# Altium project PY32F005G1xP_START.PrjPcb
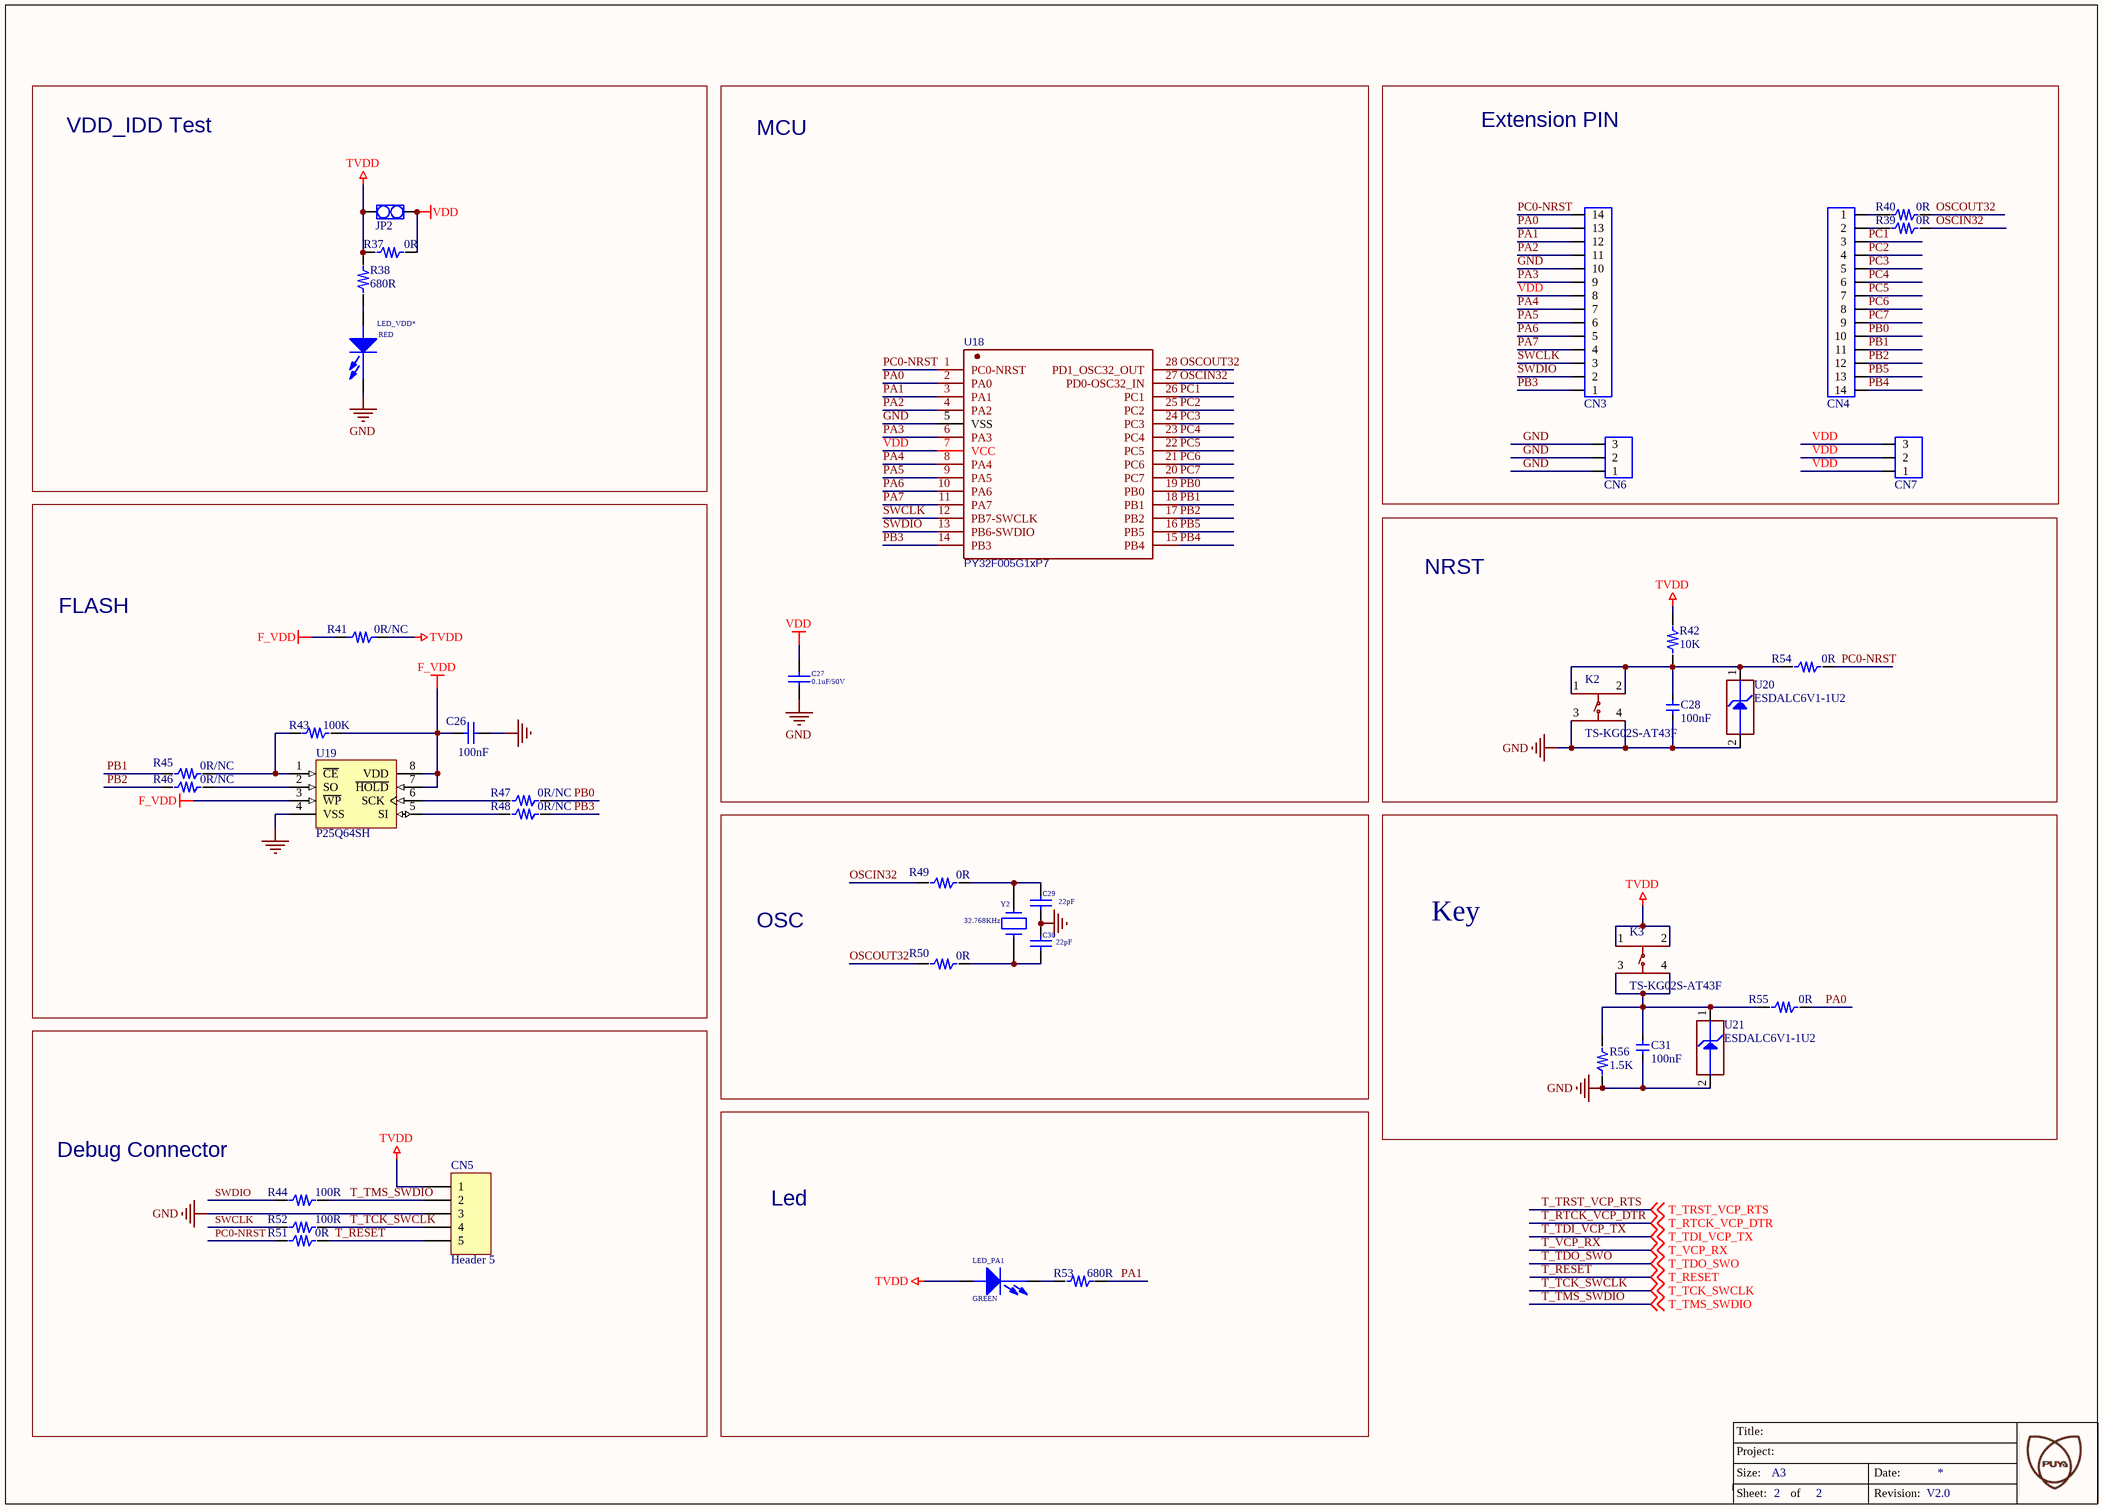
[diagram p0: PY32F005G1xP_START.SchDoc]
2 sheets, 129 parts. Net scope: global (net labels, ports and power ports of the same name join across sheets).
Board file: PY32F005G1xP_START.PcbDoc
Sheets:
  PY32F005G1xP_START.SchDoc
  PY32F403C1xT_LINK.SchDoc

## Sheet PY32F005G1xP_START.SchDoc: =DocumentName
size A3; Revision: V2.0; SheetNumber: 2; SheetTotal: 2; Project: PY32F005G1xP_START.PrjPcb

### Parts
C26  100nF  [C0603]
C27  0.1uF/50V  [0603C]
C28  100nF  [C0603]
C29  22pF  [0603C]
C30  22pF  [0603C]
C31  100nF  [C0603]
CN3  CON14  [CON14]  (value not drawn)
CN4  CON14  [CON14]  (value not drawn)
CN5  Header 5  [HDR1X5]
CN6  CON3  [CON3]  (value not drawn)
CN7  CON3  [CON3]  (value not drawn)
JP2  CON2  [CON2]  (value not drawn)
K2  TS-KG02S-AT43F  [SW-SMD_4P-L6.0-W6.0-P4.50-LS8.5]
K3  TS-KG02S-AT43F  [SW-SMD_4P-L6.0-W6.0-P4.50-LS8.5]
LED_PA1  GREEN  [0603_LED]
LED_VDD*  RED  [0603_LED]
R37  0R  [JP2_SMD]
R38  680R  [R0603]
R39  0R  [JP2_SMD]
R40  0R  [JP2_SMD]
R41  0R/NC  [JP2_SMD]
R42  10K  [R0603]
R43  100K  [R0603]
R44  100R  [JP2_SMD]
R45  0R/NC  [JP2_SMD]
R46  0R/NC  [JP2_SMD]
R47  0R/NC  [JP2_SMD]
R48  0R/NC  [JP2_SMD]
R49  0R  [JP2_SMD]
R50  0R  [JP2_SMD]
R51  0R  [JP2_SMD]
R52  100R  [JP2_SMD]
R53  680R  [R0603]
R54  0R  [JP2_SMD]
R55  0R  [JP2_SMD]
R56  1.5K  [R0603]
U18  PY32F005G1xP7  [TSSOP-28_L9.7-W4.4-P0.65-LS6.4-BL]
U19  P25Q64SH  [SOP-8P]
U20  ESDALC6V1-1U2  [ESD_ST0201]
U21  ESDALC6V1-1U2  [ESD_ST0201]
Y2  32.768KHz  [CRYSTAL-SMD_L3.2-W1.5-1]

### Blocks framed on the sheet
VDD_IDD Test: JP2 LED_VDD* R37 R38
MCU: C27 U18
Extension PIN: CN3 CN4 CN6 CN7 R39 R40
FLASH: C26 R41 R43 R45-R48 U19
NRST: C28 K2 R42 R54 U20
OSC: C29 C30 R49 R50 Y2
Key: C31 K3 R55 R56 U21
Debug Connector: CN5 R44 R51 R52
Led: LED_PA1 R53

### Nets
F_VDD: C26.2 R41.2 R43.2 U19.3(~{WP}) U19.7(~{HOLD}) U19.8(VDD)
GND: C26.1 C27.1 C28.1 C29.1 C30.2 C31.1 CN3.10 CN5.3 CN6.1 CN6.2 CN6.3 K2.3 K2.4 LED_VDD*.2(CATHODE) R56.1 U18.5(VSS) U19.4(VSS) U20.2(GND) U21.2(GND)
TVDD: CN5.1 JP2.1 K3.1 K3.2 LED_PA1.1(ANODE) R37.1 R38.2 R41.1 R42.1
VDD: C27.2 CN3.8 CN7.1 CN7.2 CN7.3 JP2.2 R37.2 U18.7(VCC)
OSCIN32: R39.1 R49.2 U18.27(PD0-OSC32_IN)
OSCOUT32: R40.1 R50.2 U18.28(PD1_OSC32_OUT)
PA0: CN3.13 R55.2 U18.2(PA0)
PA1: CN3.12 R53.2 U18.3(PA1)
PA2: CN3.11 U18.4(PA2)
PA3: CN3.9 U18.6(PA3)
PA4: CN3.7 U18.8(PA4)
PA5: CN3.6 U18.9(PA5)
PA6: CN3.5 U18.10(PA6)
PA7: CN3.4 U18.11(PA7)
PB0: CN4.10 R47.1 U18.19(PB0)
PB1: CN4.11 R45.2 U18.18(PB1)
PB2: CN4.12 R46.2 U18.17(PB2)
PB3: CN3.1 R48.1 U18.14(PB3)
PB4: CN4.14 U18.15(PB4)
PB5: CN4.13 U18.16(PB5)
PC0-NRST: CN3.14 R51.2 R54.2 U18.1(PC0-NRST)
PC1: CN4.3 U18.26(PC1)
PC2: CN4.4 U18.25(PC2)
PC3: CN4.5 U18.24(PC3)
PC4: CN4.6 U18.23(PC4)
PC5: CN4.7 U18.22(PC5)
PC6: CN4.8 U18.21(PC6)
PC7: CN4.9 U18.20(PC7)
SWCLK: CN3.3 R52.2 U18.12(PB7-SWCLK)
SWDIO: CN3.2 R44.2 U18.13(PB6-SWDIO)
T_RESET: CN5.5 R51.1 ; off-sheet T_RESET
T_TCK_SWCLK: CN5.4 R52.1 ; off-sheet T_TCK_SWCLK
T_TMS_SWDIO: CN5.2 R44.1 ; off-sheet T_TMS_SWDIO
NetC28_2: C28.2 K2.1 K2.2 R42.2 R54.1 U20.1(IO1)
NetC29_2: C29.2 R49.1 Y2.1
NetC30_1: C30.1 R50.1 Y2.2
NetC31_2: C31.2 K3.3 K3.4 R55.1 R56.2 U21.1(IO1)
NetCN4_1: CN4.1 R40.2
NetCN4_2: CN4.2 R39.2
NetLED_PA1_2: LED_PA1.2(CATHODE) R53.1
NetLED_VDD*_1: LED_VDD*.1(ANODE) R38.1
NetR43_1: R43.1 R45.1 U19.1(~{CE})
NetR46_1: R46.1 U19.2(SO)
NetR47_2: R47.2 U19.6(SCK)
NetR48_2: R48.2 U19.5(SI)

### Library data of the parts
C26 = 贴片高压陶瓷电容: Capacitor (Semiconductor SIM Model); 器件封装(外观): 0603; Value: 104
C27 = CAP: Capacitor; Value: 2.2uF
C28 C31 = C0603: PCB DECAL: 0603
C29 C30 = Cap: Capacitor
CN5 = Header 5: Header, 5-Pin
JP2 = CON2_DIP
K2 K3 = TS-KG02S-AT43F: Manufacturer: HANBO(汉博); Add into BOM: yes; Circuit: 单刀单掷; Actuator Style: 圆形按钮; Operating Force: 250gf; Switch Length: 6mm; Switch Height: 4.3mm; Strike Gundam: 不带; Contact Current: 50mA; Voltage Rating (DC): 12V; Insulation Resistance: 100MΩ; Actuator/Cap Color: 黑色; Pin Style: 鸥翼型
LED_PA1 LED_VDD* = PDI-E803_Dup1
R37-R56 = R0603: PCB DECAL: 0603
U18 = PY32F005G1xP7: TSSOP28(9.7*4.4); BOM_Manufacturer: PUYA(普冉)
U19 = SST25VF010: Value: SST25VF020B; 器件封装(外观): SOP8
U20 U21 = ESDALC6V1-1U2: ESD protection 6V1; Internal_Part_Number: MCD-00170; Part_Type: Diode; Manufacturer: STMICROELECTRONICS; ECCN_US: EAR99; ECCN_EU: NEC; Provided_By: Subcon; Initial_Board_Reference: MB1274
Y2 = CRYSTAL_1: Crystal; Value: X503225MSB2GI

## Sheet PY32F403C1xT_LINK.SchDoc: =DocumentName
size A3; Revision: V2.0; SheetNumber: 1; SheetTotal: 2; Project: PY32F005G1xP_START.PrjPcb
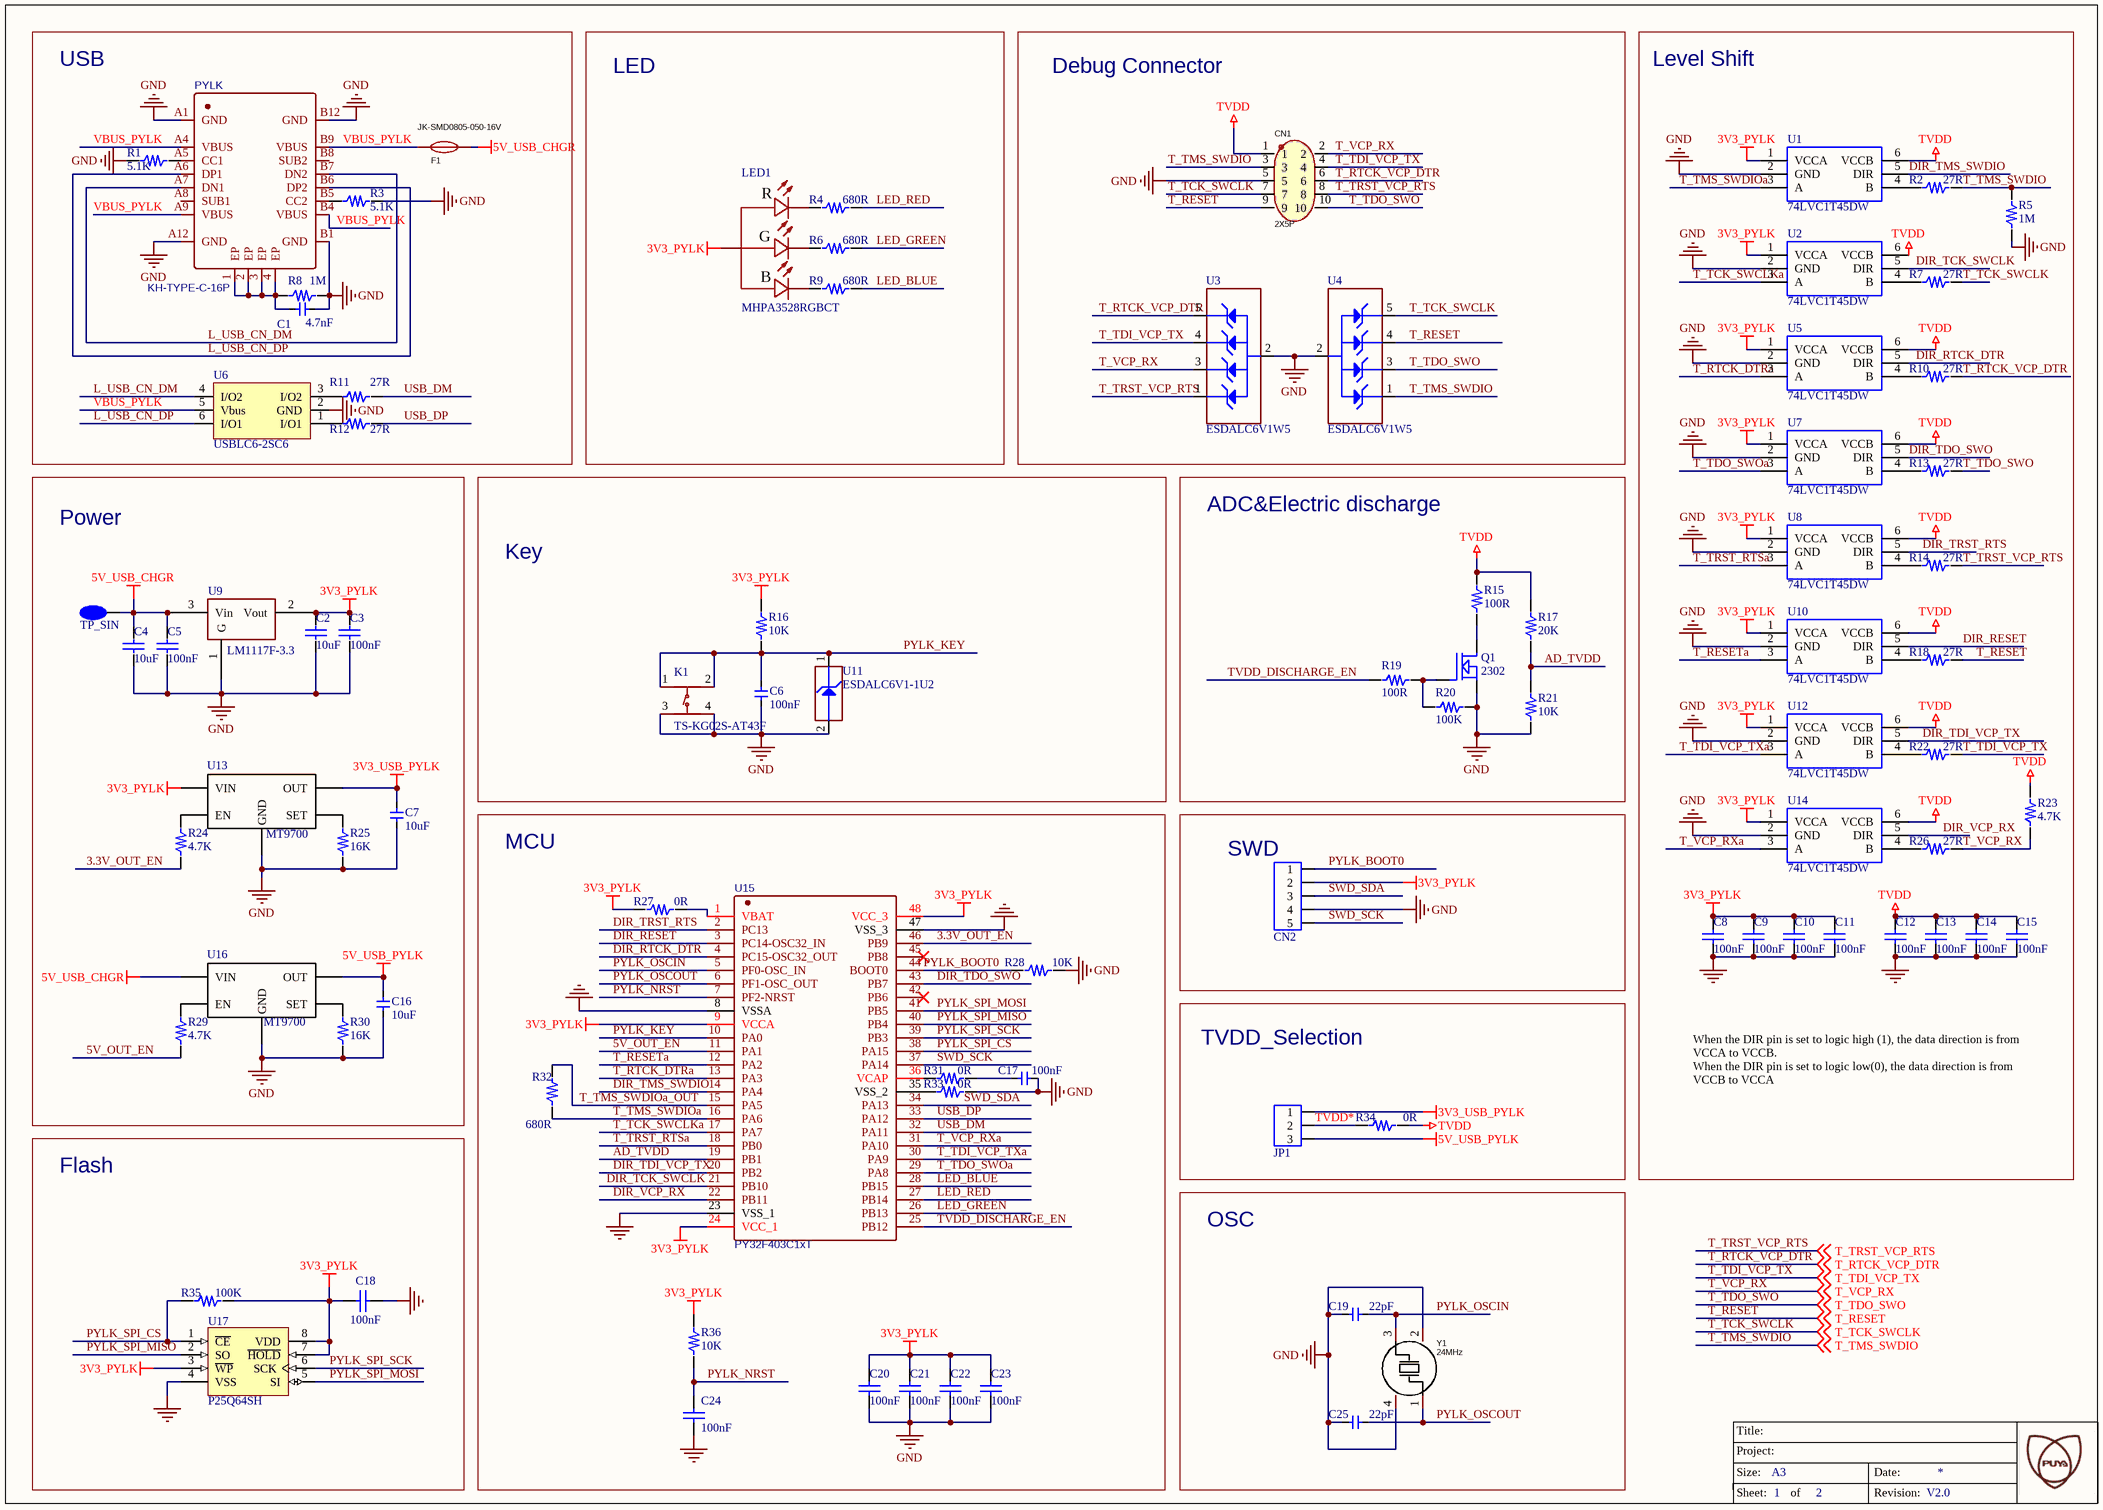
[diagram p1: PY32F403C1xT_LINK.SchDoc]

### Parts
1  TP_SIN  [TP_SIN]
C1  4.7nF  [C0603]
C2  10uF  [C0805]
C3  100nF  [C0603]
C4  10uF  [C0805]
C5  100nF  [C0603]
C6  100nF  [C0603]
C7  10uF  [C0805]
C8  100nF  [C0603]
C9  100nF  [C0603]
C10  100nF  [C0603]
C11  100nF  [C0603]
C12  100nF  [C0603]
C13  100nF  [C0603]
C14  100nF  [C0603]
C15  100nF  [C0603]
C16  10uF  [C0805]
C17  100nF  [C0603]
C18  100nF  [C0603]
C19  22pF  [C0603]
C20  100nF  [C0603]
C21  100nF  [C0603]
C22  100nF  [C0603]
C23  100nF  [C0603]
C24  100nF  [C0603]
C25  22pF  [C0603]
CN1  2X5P  [HDR2X5]
CN2  CON5  [CON5]  (value not drawn)
F1  JK-SMD0805-050-16V  [F0805]
JP1  CON3  [CON3]  (value not drawn)
K1  TS-KG02S-AT43F  [SW-SMD_4P-L6.0-W6.0-P4.50-LS8.5]
LED1  MHPA3528RGBCT  [LED-ARRAY-SMD_4P-L3.5-W2.8-TL]
PYLK  KH-TYPE-C-16P  [USB-C-SMD_KH-TYPE-C-16P]
Q1  2302  [SOT23]
R1  5.1K  [R0603]
R2  27R  [R0603]
R3  5.1K  [R0603]
R4  680R  [R0603]
R5  1M  [R0603]
R6  680R  [R0603]
R7  27R  [R0603]
R8  1M  [R0603]
R9  680R  [R0603]
R10  27R  [R0603]
R11  27R  [R0603]
R12  27R  [R0603]
R13  27R  [R0603]
R14  27R  [R0603]
R15  100R  [R0805]
R16  10K  [R0603]
R17  20K  [R0603]
R18  27R  [R0603]
R19  100R  [R0603]
R20  100K  [R0603]
R21  10K  [R0603]
R22  27R  [R0603]
R23  4.7K  [R0603]
R24  4.7K  [R0603]
R25  16K  [R0603]
R26  27R  [R0603]
R27  0R  [JP2_SMD]
R28  10K  [R0603]
R29  4.7K  [R0603]
R30  16K  [R0603]
R31  0R  [JP2_SMD]
R32  680R  [R0603]
R33  0R  [JP2_SMD]
R34  0R  [JP2_SMD]
R35  100K  [R0603]
R36  10K  [R0603]
U1  74LVC1T45DW  [SOT363]
U2  74LVC1T45DW  [SOT363]
U3  value ESDALC6V1W5  [ESD_SOT323-5L]  (hidden comment: ESD_6V1)
U4  value ESDALC6V1W5  [ESD_SOT323-5L]  (hidden comment: ESD_6V1)
U5  74LVC1T45DW  [SOT363]
U6  USBLC6-2SC6  [SOT23-6]
U7  74LVC1T45DW  [SOT363]
U8  74LVC1T45DW  [SOT363]
U9  LM1117F-3.3  [SOT-89-3_L4.5-W2.5-P1.50-LS4.2-BR]
U10  74LVC1T45DW  [SOT363]
U11  ESDALC6V1-1U2  [ESD_ST0201]
U12  74LVC1T45DW  [SOT363]
U13  MT9700  [SOT23-5]
U14  74LVC1T45DW  [SOT363]
U15  PY32F403C1xT  [LQFP-48_L7.0-W7.0-P0.50-LS9.0-BL]
U16  MT9700  [SOT23-5]
U17  P25Q64SH  [SOP-8P]
Y1  24MHz  [CRYSTAL-SMD_4P-L3.2-W2.5-BL]

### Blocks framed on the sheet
USB: C1 F1 PYLK R1 R3 R8 R11 R12 U6
LED: LED1 R4 R6 R9
Debug Connector: CN1 U3 U4
Level Shift: C8-C15 R2 R5 R7 R10 R13 R14 R18 R22 R23 R26 U1 U2 U5 U7 U8 U10 U12 U14
Power: 1 C2-C5 C7 C16 R24 R25 R29 R30 U9 U13 U16
Key: C6 K1 R16 U11
ADC&Electric discharge: Q1 R15 R17 R19-R21
MCU: C17 C20-C24 R27 R28 R31-R33 R36 U15
SWD: CN2
TVDD_Selection: JP1 R34
Flash: C18 R35 U17
OSC: C19 C25 Y1

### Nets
3V3_PYLK: C2.2 C3.2 C8.2 C9.2 C10.2 C11.2 C18.2 C20.2 C21.2 C22.2 C23.2 CN2.2 LED1.1(-) R16.2 R27.1 R35.2 R36.2 U1.1(VCCA) U2.1(VCCA) U5.1(VCCA) U7.1(VCCA) U8.1(VCCA) U9.2(Vout) U10.1(VCCA) U12.1(VCCA) U13.5(VIN) U14.1(VCCA) U15.9(VCCA) U15.24(VCC_1) U15.48(VCC_3) U17.3(~{WP}) U17.7(~{HOLD}) U17.8(VDD)
3V3_USB_PYLK: C7.2 JP1.1 U13.1(OUT)
5V_USB_CHGR: 1.1(TP_SIN) C4.2 C5.2 F1.2 U9.3(Vin) U16.5(VIN)
5V_USB_PYLK: C16.2 JP1.3 U16.1(OUT)
GND: C1.1 C2.1 C3.1 C4.1 C5.1 C6.1 C7.1 C8.1 C9.1 C10.1 C11.1 C12.1 C13.1 C14.1 C15.1 C16.1 C17.1 C18.1 C19.1 C20.1 C21.1 C22.1 C23.1 C24.1 C25.1 CN1.5 CN2.4 K1.3 K1.4 PYLK.A1(GND) PYLK.A12(GND) PYLK.B1(GND) PYLK.B12(GND) Q1.2(S) R1.1 R3.2 R5.1 R8.2 R20.1 R21.1 R25.1 R28.2 R30.1 R33.2 U1.2(GND) U2.2(GND) U3.2(GND) U4.2(GND) U5.2(GND) U6.2(GND) U7.2(GND) U8.2(GND) U9.1(G) U10.2(GND) U11.2(GND) U12.2(GND) U13.2(GND) U14.2(GND) U15.8(VSSA) U15.23(VSS_1) U15.47(VSS_3) U16.2(GND) U17.4(VSS) Y1.2(GND) Y1.4(GND)
TVDD: C12.2 C13.2 C14.2 C15.2 CN1.1 R15.2 R17.2 R23.2 R34.2 U1.6(VCCB) U2.6(VCCB) U5.6(VCCB) U7.6(VCCB) U8.6(VCCB) U10.6(VCCB) U12.6(VCCB) U14.6(VCCB)
3.3V_OUT_EN: R24.1 U15.46(PB9)
5V_OUT_EN: R29.1 U15.11(PA1)
AD_TVDD: R17.1 R21.2 U15.19(PB1)
DIR_RESET: U10.5(DIR) U15.3(PC14-OSC32_IN)
DIR_RTCK_DTR: U5.5(DIR) U15.4(PC15-OSC32_OUT)
DIR_TCK_SWCLK: U2.5(DIR) U15.21(PB10)
DIR_TDI_VCP_TX: U12.5(DIR) U15.20(PB2)
DIR_TDO_SWO: U7.5(DIR) U15.43(PB7)
DIR_TMS_SWDIO: U1.5(DIR) U15.14(PA4)
DIR_TRST_RTS: U8.5(DIR) U15.2(PC13)
DIR_VCP_RX: U14.5(DIR) U15.22(PB11)
L_USB_CN_DM: PYLK.A7(DN1) PYLK.B7(DN2) U6.4(I/O2)
L_USB_CN_DP: PYLK.A6(DP1) PYLK.B6(DP2) U6.6(I/O1)
LED_BLUE: R9.2 U15.28(PB15)
LED_GREEN: R6.2 U15.26(PB13)
LED_RED: R4.2 U15.27(PB14)
PYLK_BOOT0: CN2.1 R28.1 U15.44(BOOT0)
PYLK_KEY: C6.2 K1.1 K1.2 R16.1 U11.1(IO1) U15.10(PA0)
PYLK_NRST: C24.2 R36.1 U15.7(PF2-NRST)
PYLK_OSCIN: C19.2 U15.5(PF0-OSC_IN) Y1.3(OSC2)
PYLK_OSCOUT: C25.2 U15.6(PF1-OSC_OUT) Y1.1(OSC1)
PYLK_SPI_CS: R35.1 U15.38(PA15) U17.1(~{CE})
PYLK_SPI_MISO: U15.40(PB4) U17.2(SO)
PYLK_SPI_MOSI: U15.41(PB5) U17.5(SI)
PYLK_SPI_SCK: U15.39(PB3) U17.6(SCK)
SWD_SCK: CN2.5 U15.37(PA14)
SWD_SDA: CN2.3 U15.34(PA13)
T_RESET: CN1.9 R18.2 U4.4(IO3) ; off-sheet T_RESET
T_RESETa: U10.3(A) U15.12(PA2)
T_RTCK_DTRa: U5.3(A) U15.13(PA3)
T_RTCK_VCP_DTR: CN1.6 R10.2 U3.5(IO4) ; off-sheet T_RTCK_VCP_DTR
T_TCK_SWCLK: CN1.7 R7.2 U4.5(IO4) ; off-sheet T_TCK_SWCLK
T_TCK_SWCLKa: U2.3(A) U15.17(PA7)
T_TDI_VCP_TX: CN1.4 R22.2 U3.4(IO3) ; off-sheet T_TDI_VCP_TX
T_TDI_VCP_TXa: U12.3(A) U15.30(PA9)
T_TDO_SWO: CN1.10 R13.2 U4.3(IO2) ; off-sheet T_TDO_SWO
T_TDO_SWOa: U7.3(A) U15.29(PA8)
T_TMS_SWDIO: CN1.3 R2.2 R5.2 U4.1(IO1) ; off-sheet T_TMS_SWDIO
T_TMS_SWDIOa: R32.1 U1.3(A) U15.16(PA6)
T_TMS_SWDIOa_OUT: R32.2 U15.15(PA5)
T_TRST_RTSa: U8.3(A) U15.18(PB0)
T_TRST_VCP_RTS: CN1.8 R14.2 U3.1(IO1) ; off-sheet T_TRST_VCP_RTS
T_VCP_RX: CN1.2 R23.1 R26.2 U3.3(IO2) ; off-sheet T_VCP_RX
T_VCP_RXa: U14.3(A) U15.31(PA10)
TVDD*: JP1.2 R34.1
TVDD_DISCHARGE_EN: R19.2 U15.25(PB12)
USB_DM: R11.2 U15.32(PA11)
USB_DP: R12.2 U15.33(PA12)
VBUS_PYLK: F1.1 PYLK.A4(VBUS) PYLK.A9(VBUS) PYLK.B4(VBUS) PYLK.B9(VBUS) U6.5(Vbus)
NetC1_2: C1.2 PYLK.1(EP) PYLK.2(EP) PYLK.3(EP) PYLK.4(EP) R8.1
NetC17_2: C17.2 R31.2
NetLED1_2: LED1.2(-) R9.1
NetLED1_3: LED1.3(-) R6.1
NetLED1_4: LED1.4(-) R4.1
NetPYLK_A5: PYLK.A5(CC1) R1.2
NetPYLK_B5: PYLK.B5(CC2) R3.1
NetQ1_1: Q1.1(G) R19.1 R20.2
NetQ1_3: Q1.3(D) R15.1
NetR2_1: R2.1 U1.4(B)
NetR7_1: R7.1 U2.4(B)
NetR10_1: R10.1 U5.4(B)
NetR11_1: R11.1 U6.3(I/O2)
NetR12_1: R12.1 U6.1(I/O1)
NetR13_1: R13.1 U7.4(B)
NetR14_1: R14.1 U8.4(B)
NetR18_1: R18.1 U10.4(B)
NetR22_1: R22.1 U12.4(B)
NetR24_2: R24.2 U13.4(EN)
NetR25_2: R25.2 U13.3(SET)
NetR26_1: R26.1 U14.4(B)
NetR27_2: R27.2 U15.1(VBAT)
NetR29_2: R29.2 U16.4(EN)
NetR30_2: R30.2 U16.3(SET)
NetR31_1: R31.1 U15.36(VCAP)
NetR33_1: R33.1 U15.35(VSS_2)

Not connected (* = marked no-connect by the designer): PYLK A8(SUB1) B8(SUB2); U15 42(PB6)* 45(PB8)*

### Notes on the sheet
- When the DIR pin is set to logic high (1), the data direction is from VCCA to VCCB.
  When the DIR pin is set to logic low(0), the data direction is from VCCB to VCCA

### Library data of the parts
C1 C3 C5 C6 C17 C19 C25 = C0603: PCB DECAL: 0603
C2 C4 C7 C16 = C0805: PCB DECAL: 0805
C8-C15 C18 C20-C24 = 贴片高压陶瓷电容: as C26 on sheet PY32F005G1xP_START
CN1 = 2X5P: Manufacturer: XFCN(兴飞); Symbol: PZ254V-12-10P; Add into BOM: yes; Pitch: 2.54mm; Circluar Pins/Square Pins: 方针
F1 = JK-SMD0805-050-16V: Manufacturer: JK(金科); Add into BOM: yes; Voltage - Max: 6V; Current - Max: 100A; Hold Current: 500mA; Trip Current: 1A; Power Dissipation: 600mW; Resistance - Initial (Ri) (Min): 150mΩ; Resistance - Post Trip (R1) (Max): 850mΩ; Time to Trip(Max): 100ms
K1 = TS-KG02S-AT43F: as K2 on sheet PY32F005G1xP_START
LED1 = MHPA3528RGBCT: Manufacturer: MEIHUA(美华); Add into BOM: yes
PYLK = KH-TYPE-C-16P: BOM_Manufacturer: Shenzhen Kinghelm Elec; Contributor: LCSC
Q1 = MOSFET N: Value: SI2302
R1-R14 R16-R24 R26-R29 R31-R36 = R0603: PCB DECAL: 0603
R15 = R0805: PCB DECAL: 0805
R25 R30 = R0603_7: 0603WAF1602T5E 16KΩ(1602) ±1%; PCB DECAL: 0603
U3 U4 = ESDALC6V1W5: Dual Transil array for ESD protection; Internal_Part_Number: MCD-00136; Part_Type: Diode; Manufacturer: STMICROELECTRONICS; ECCN_US: EAR99; ECCN_EU: NEC; Provided_By: Subcon; Initial_Board_Reference: MB1262
U6 = USBLC6-2SC6: Function: ESD EMI fliter
U11 = ESDALC6V1-1U2: as U20 on sheet PY32F005G1xP_START
U15 = PY32F403C1xT: LQFP48; BOM_Manufacturer: PUYA(普冉)
U17 = SST25VF010: Value: SST25VF020B; 器件封装(外观): SOP8
Y1 = ABM8AIG-24.000MHZ-82Z-T: ±20ppm , 12.5pF , T_use: -40°C~125°C; Manufacturer: ABRACON; Add into BOM: yes; External load capacitor: 8pF; Frequency Stability(Full temperature range): ±50ppm; Equivalent Series Resistance (ESR): 50Ω

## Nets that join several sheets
GND: PY32F005G1xP_START (19 pins), PY32F403C1xT_LINK (65 pins)
TVDD: PY32F005G1xP_START (9 pins), PY32F403C1xT_LINK (17 pins)
T_RESET: PY32F005G1xP_START (CN5.5 R51.1), PY32F403C1xT_LINK (CN1.9 R18.2 U4.4)
T_TCK_SWCLK: PY32F005G1xP_START (CN5.4 R52.1), PY32F403C1xT_LINK (CN1.7 R7.2 U4.5)
T_TMS_SWDIO: PY32F005G1xP_START (CN5.2 R44.1), PY32F403C1xT_LINK (CN1.3 R2.2 R5.2 U4.1)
